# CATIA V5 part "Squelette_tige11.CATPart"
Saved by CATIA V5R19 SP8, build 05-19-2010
Part number: Squelette_tige11
Bounding box of the stored display mesh (mm): x 20 to 130, y 20 to 20, z 20 to 20
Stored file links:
  G:\EU_thinkMotion\CFAO_2010\MMS_groupe2\MMS_groupe2\A reprendre\jcauchy\Squelette_tige11.CATPart
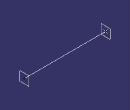
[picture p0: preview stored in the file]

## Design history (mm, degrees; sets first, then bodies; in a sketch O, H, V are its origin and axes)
Parameters
  Longueurtige_tige11 = 110 mm
Set1
  Point1: (20, 20, 20)
  Line1: type PtDir, RefPoint Point1, Direction yz-plane, Start 0, End 110 {= Longueurtige_tige11}
  Plane1: type Normal, Curve Line1, RefPoint Point1
  Plane2: type Normal, Curve Line1, RefPoint vertex of Line1
Body1 (main body)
